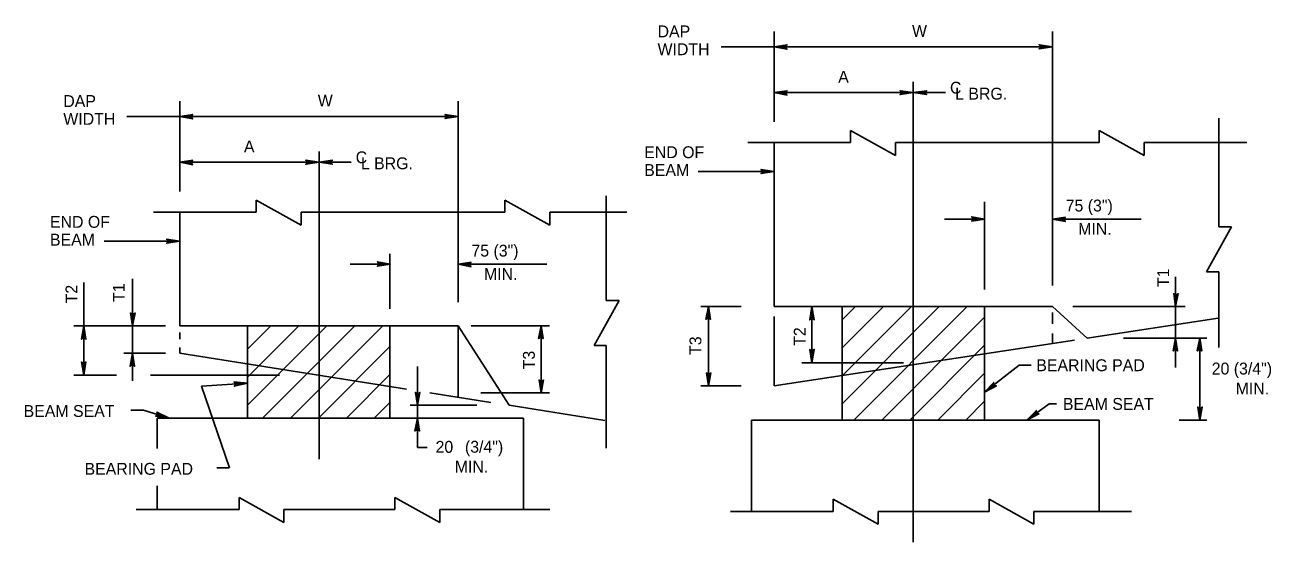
# Model space of a CAD drawing. Extents: x 637933 to 640019, y 298854 to 300042.
# Drawn here: x 639703.7 to 640018.8, y 299316.2 to 299446.8 of the extents above; entities that cross this region are included whole.
import ezdxf

# ---------------------------------------------------------------- set-up
doc = ezdxf.new("R2010")
doc.units = 0
doc.layers.add('1', color=7, linetype='Continuous')

msp = doc.modelspace()

# ---------------------------------------------------------------- linework, layer by layer
at = {"layer": '1'}
for p, q in [((639893.14, 299445.19), (639893.14, 299422.36)), ((639963.49, 299445.19), (639963.49, 299380.98)), ((639879.74, 299441.32), (639963.49, 299441.32)), ((639928.31, 299432.46), (639928.31, 299426.1)), ((639893.14, 299429.72), (639928.31, 299429.72)), ((639928.31, 299429.72), (639936.45, 299429.72)), ((639742.9, 299427.6), (639742.9, 299404.77)), ((639813.25, 299427.6), (639813.25, 299376.85)), ((639729.5, 299423.73), (639813.25, 299423.73)), ((639928.31, 299316.23), (639928.31, 299426.1)), ((640005.52, 299395.86), (640005.52, 299423.24)), ((639912.44, 299417.13), (639912.44, 299420.19)), ((639912.44, 299420.19), (639923.79, 299413.88)), ((639975.28, 299417.13), (639975.28, 299420.19)), ((639975.28, 299420.19), (639986.63, 299413.88)), ((639886.44, 299417.13), (639912.44, 299417.13)), ((639893.14, 299417.13), (639893.14, 299375.72)), ((639923.79, 299417.13), (639975.28, 299417.13)), ((639923.79, 299417.13), (639923.79, 299413.88)), ((639986.63, 299417.13), (639986.63, 299413.88)), ((639986.63, 299417.13), (640012.63, 299417.13)), ((639778.07, 299414.87), (639778.07, 299408.51)), ((639778.07, 299337.19), (639778.07, 299414.78)), ((639742.9, 299412.13), (639778.07, 299412.13)), ((639778.07, 299412.13), (639786.21, 299412.13)), ((639873.94, 299409.78), (639893.14, 299409.78)), ((639762.2, 299399.54), (639762.2, 299402.6)), ((639762.2, 299402.6), (639773.55, 299396.29)), ((639825.04, 299399.54), (639825.04, 299402.6)), ((639825.04, 299402.6), (639836.39, 299396.29)), ((639850.69, 299377.25), (639850.69, 299403.63)), ((639946.31, 299379.97), (639946.31, 299402.14)), ((639736.2, 299399.54), (639762.2, 299399.54)), ((639742.9, 299399.54), (639742.9, 299370.85)), ((639773.55, 299399.54), (639825.04, 299399.54)), ((639773.55, 299399.54), (639773.55, 299396.29)), ((639836.39, 299399.54), (639836.39, 299396.29)), ((639836.39, 299399.54), (639855.87, 299399.54)), ((639946.31, 299397.77), (639936.21, 299397.77)), ((639963.49, 299397.77), (639985.91, 299397.77)), ((640002.46, 299384.51), (640008.77, 299395.86)), ((640005.52, 299395.86), (640008.77, 299395.86)), ((639723.7, 299392.19), (639742.9, 299392.19)), ((639795.98, 299375.11), (639795.98, 299389.04)), ((639796.07, 299386.38), (639785.97, 299386.38)), ((639813.25, 299386.38), (639835.67, 299386.38)), ((639730.92, 299382.69), (639730.92, 299370.85)), ((639994.63, 299383.17), (639994.63, 299375.72)), ((640005.52, 299384.51), (640002.46, 299384.51)), ((640005.52, 299365.37), (640005.52, 299384.51)), ((639718.57, 299381.75), (639718.57, 299370.85)), ((639847.63, 299365.9), (639853.94, 299377.25)), ((639850.69, 299377.25), (639853.94, 299377.25)), ((639874.56, 299375.72), (639884.81, 299375.72)), ((639876.51, 299375.72), (639876.51, 299355.71)), ((639963.49, 299375.72), (639893.14, 299375.72)), ((639893.14, 299373.16), (639893.14, 299355.71)), ((639902.69, 299375.72), (639902.69, 299361.5)), ((639910.31, 299347.05), (639910.31, 299375.72)), ((639910.31, 299372.37), (639913.66, 299375.72)), ((639910.31, 299365.3), (639920.73, 299375.72)), ((639910.31, 299358.23), (639927.81, 299375.72)), ((639910.31, 299351.16), (639934.88, 299375.72)), ((639913.27, 299347.05), (639941.95, 299375.72)), ((639920.34, 299347.05), (639946.31, 299373.02)), ((639946.31, 299347.05), (639946.31, 299375.72)), ((639963.49, 299375.72), (639972.26, 299367.73)), ((639963.49, 299374.18), (639963.49, 299371.3)), ((639968.6, 299375.72), (639997.05, 299375.72)), ((639972.26, 299367.73), (640005.38, 299372.76)), ((639994.63, 299375.72), (639994.63, 299367.73)), ((639716.03, 299370.85), (639739.23, 299370.85)), ((639718.57, 299370.85), (639718.57, 299358.34)), ((639730.92, 299370.85), (639730.92, 299363.89)), ((639813.25, 299370.85), (639742.9, 299370.85)), ((639759.98, 299347.52), (639759.98, 299370.85)), ((639759.98, 299364.95), (639765.88, 299370.85)), ((639759.98, 299357.88), (639772.95, 299370.85)), ((639759.98, 299350.81), (639780.02, 299370.85)), ((639763.75, 299347.52), (639787.09, 299370.85)), ((639770.83, 299347.52), (639794.17, 299370.85)), ((639795.98, 299347.52), (639795.98, 299370.85)), ((639813.25, 299370.85), (639826.13, 299350.77)), ((639813.25, 299370.85), (639813.25, 299352.8)), ((639816.5, 299370.85), (639836.33, 299370.85)), ((639834.21, 299370.85), (639834.21, 299353.94)), ((639742.9, 299369.17), (639742.9, 299367.48)), ((639893.14, 299355.71), (639969.06, 299367.24)), ((639963.49, 299368.87), (639963.49, 299366.4)), ((639981.41, 299367.73), (640002.5, 299367.73)), ((639994.63, 299367.73), (639994.63, 299360.33)), ((640000.71, 299367.73), (640000.71, 299347.05)), ((639728.75, 299363.89), (639739.23, 299363.89)), ((639730.92, 299363.89), (639730.92, 299356.9)), ((639742.9, 299365.33), (639742.9, 299363.89)), ((639742.9, 299363.89), (639800.19, 299354.86)), ((639777.9, 299347.52), (639795.98, 299365.6)), ((639850.69, 299365.9), (639847.63, 299365.9)), ((639850.69, 299339.9), (639850.69, 299365.9)), ((639927.42, 299347.05), (639946.31, 299365.94)), ((639802.94, 299360.6), (639802.94, 299350.77)), ((639900.15, 299361.5), (639925.8, 299361.5)), ((639716.03, 299358.34), (639726.88, 299358.34)), ((639735.49, 299358.34), (639768.05, 299358.34)), ((639784.97, 299347.52), (639795.98, 299358.53)), ((639934.49, 299347.05), (639946.31, 299358.87)), ((639748.36, 299355.61), (639755.39, 299335)), ((639806.06, 299353.93), (639821.52, 299351.49)), ((639819, 299353.94), (639836.33, 299353.94)), ((639874.56, 299355.71), (639884.81, 299355.71)), ((639792.04, 299347.52), (639795.98, 299351.46)), ((639801.06, 299350.77), (639817.97, 299350.77)), ((639802.94, 299350.77), (639802.94, 299347.52)), ((639826.13, 299350.77), (639850.31, 299346.96)), ((639941.56, 299347.05), (639946.31, 299351.8)), ((639730.5, 299349.54), (639733.67, 299349.54)), ((639733.67, 299349.54), (639740.14, 299347.52)), ((639737.13, 299347.52), (639829.76, 299347.52)), ((639737.13, 299347.52), (639737.13, 299339.88)), ((639802.94, 299347.52), (639802.94, 299340.1)), ((639829.76, 299347.52), (639829.76, 299324.45)), ((639887.37, 299347.05), (639887.37, 299323.98)), ((639887.37, 299347.05), (639975.26, 299347.05)), ((639975.26, 299347.05), (639975.26, 299323.98)), ((640002.5, 299347.05), (639995.53, 299347.05)), ((639802.94, 299340.1), (639805.42, 299340.1)), ((639752.22, 299335), (639755.38, 299335)), ((639737.13, 299330.45), (639737.13, 299324.45)), ((639757.84, 299324.45), (639757.84, 299327.5)), ((639757.84, 299327.5), (639769.19, 299321.2)), ((639797.22, 299324.45), (639797.22, 299327.5)), ((639797.22, 299327.5), (639808.57, 299321.2)), ((639908.08, 299323.98), (639908.08, 299327.04)), ((639908.08, 299327.04), (639919.43, 299320.73)), ((639947.46, 299323.98), (639947.46, 299327.04)), ((639947.46, 299327.04), (639958.81, 299320.73)), ((639731.84, 299324.45), (639757.84, 299324.45)), ((639769.19, 299324.45), (639797.22, 299324.45)), ((639769.19, 299324.45), (639769.19, 299321.2)), ((639808.57, 299324.45), (639808.57, 299321.2)), ((639808.57, 299324.45), (639836.43, 299324.45)), ((639882.08, 299323.98), (639908.08, 299323.98)), ((639919.43, 299323.98), (639947.46, 299323.98)), ((639919.43, 299323.98), (639919.43, 299320.73)), ((639958.81, 299323.98), (639958.81, 299320.73)), ((639958.81, 299323.98), (639983.46, 299323.98))]:
    msp.add_line(p, q, dxfattribs=at)
for points in [[(639896.26, 299440.82), (639896.14, 299441.07), (639893.14, 299441.32), (639896.26, 299440.82), (639896.39, 299440.69), (639893.14, 299441.32), (639896.14, 299441.44), (639896.26, 299441.69), (639893.14, 299441.32), (639896.39, 299441.82), (639896.26, 299441.69)], [(639960.37, 299441.69), (639960.49, 299441.44), (639963.49, 299441.32), (639960.37, 299441.69), (639960.12, 299441.82), (639963.49, 299441.32), (639960.49, 299441.19), (639960.37, 299440.94), (639963.49, 299441.32), (639960.12, 299440.82), (639960.37, 299440.94)], [(639896.26, 299429.22), (639896.14, 299429.47), (639893.14, 299429.72), (639896.26, 299429.22), (639896.39, 299429.09), (639893.14, 299429.72), (639896.14, 299429.84), (639896.26, 299430.09), (639893.14, 299429.72), (639896.39, 299430.22), (639896.26, 299430.09)], [(639925.19, 299430.09), (639925.31, 299429.84), (639928.31, 299429.72), (639925.19, 299430.09), (639924.94, 299430.22), (639928.31, 299429.72), (639925.31, 299429.59), (639925.19, 299429.34), (639928.31, 299429.72), (639924.94, 299429.22), (639925.19, 299429.34)], [(639931.44, 299430.09), (639931.31, 299429.84), (639928.31, 299429.72), (639931.44, 299430.09), (639931.69, 299430.22), (639928.31, 299429.72), (639931.31, 299429.59), (639931.44, 299429.34), (639928.31, 299429.72), (639931.69, 299429.22), (639931.44, 299429.34)], [(639746.02, 299423.23), (639745.9, 299423.48), (639742.9, 299423.73), (639746.02, 299423.23), (639746.15, 299423.1), (639742.9, 299423.73), (639745.9, 299423.85), (639746.02, 299424.1), (639742.9, 299423.73), (639746.15, 299424.23), (639746.02, 299424.1)], [(639810.12, 299424.1), (639810.25, 299423.85), (639813.25, 299423.73), (639810.12, 299424.1), (639809.87, 299424.23), (639813.25, 299423.73), (639810.25, 299423.6), (639810.12, 299423.35), (639813.25, 299423.73), (639809.87, 299423.23), (639810.12, 299423.35)], [(639746.02, 299411.63), (639745.9, 299411.88), (639742.9, 299412.13), (639746.02, 299411.63), (639746.15, 299411.5), (639742.9, 299412.13), (639745.9, 299412.25), (639746.02, 299412.5), (639742.9, 299412.13), (639746.15, 299412.63), (639746.02, 299412.5)], [(639774.95, 299412.5), (639775.07, 299412.25), (639778.07, 299412.13), (639774.95, 299412.5), (639774.7, 299412.63), (639778.07, 299412.13), (639775.07, 299412), (639774.95, 299411.75), (639778.07, 299412.13), (639774.7, 299411.63), (639774.95, 299411.75)], [(639781.2, 299412.5), (639781.07, 299412.25), (639778.07, 299412.13), (639781.2, 299412.5), (639781.45, 299412.63), (639778.07, 299412.13), (639781.07, 299412), (639781.2, 299411.75), (639778.07, 299412.13), (639781.45, 299411.63), (639781.2, 299411.75)], [(639890.01, 299410.15), (639890.14, 299409.9), (639893.14, 299409.78), (639890.01, 299410.15), (639889.76, 299410.28), (639893.14, 299409.78), (639890.14, 299409.65), (639890.01, 299409.4), (639893.14, 299409.78), (639889.76, 299409.28), (639890.01, 299409.4)], [(639943.19, 299398.27), (639943.31, 299398.02), (639946.31, 299397.77), (639943.19, 299398.27), (639943.06, 299398.39), (639946.31, 299397.77), (639943.31, 299397.64), (639943.19, 299397.39), (639946.31, 299397.77), (639943.06, 299397.27), (639943.19, 299397.39)], [(639966.62, 299397.27), (639966.49, 299397.52), (639963.49, 299397.77), (639966.62, 299397.27), (639966.74, 299397.14), (639963.49, 299397.77), (639966.49, 299397.89), (639966.62, 299398.14), (639963.49, 299397.77), (639966.74, 299398.27), (639966.62, 299398.14)], [(639739.77, 299392.57), (639739.9, 299392.32), (639742.9, 299392.19), (639739.77, 299392.57), (639739.52, 299392.69), (639742.9, 299392.19), (639739.9, 299392.07), (639739.77, 299391.82), (639742.9, 299392.19), (639739.52, 299391.69), (639739.77, 299391.82)], [(639792.95, 299386.88), (639793.07, 299386.63), (639796.07, 299386.38), (639792.95, 299386.88), (639792.82, 299387), (639796.07, 299386.38), (639793.07, 299386.25), (639792.95, 299386), (639796.07, 299386.38), (639792.82, 299385.88), (639792.95, 299386)], [(639816.37, 299385.88), (639816.25, 299386.13), (639813.25, 299386.38), (639816.37, 299385.88), (639816.5, 299385.75), (639813.25, 299386.38), (639816.25, 299386.5), (639816.37, 299386.75), (639813.25, 299386.38), (639816.5, 299386.88), (639816.37, 299386.75)], [(639995.13, 299378.85), (639994.88, 299378.72), (639994.63, 299375.72), (639995.13, 299378.85), (639995.26, 299378.97), (639994.63, 299375.72), (639994.51, 299378.72), (639994.26, 299378.85), (639994.63, 299375.72), (639994.13, 299378.97), (639994.26, 299378.85)], [(639731.42, 299373.98), (639731.17, 299373.85), (639730.92, 299370.85), (639731.42, 299373.98), (639731.55, 299374.1), (639730.92, 299370.85), (639730.8, 299373.85), (639730.55, 299373.98), (639730.92, 299370.85), (639730.42, 299374.1), (639730.55, 299373.98)], [(639876.01, 299372.6), (639876.26, 299372.72), (639876.51, 299375.72), (639876.01, 299372.6), (639875.89, 299372.47), (639876.51, 299375.72), (639876.64, 299372.72), (639876.89, 299372.6), (639876.51, 299375.72), (639877.01, 299372.47), (639876.89, 299372.6)], [(639902.28, 299372.49), (639902.52, 299372.61), (639902.69, 299375.72), (639902.28, 299372.49), (639902.14, 299372.33), (639902.69, 299375.72), (639902.84, 299372.62), (639903.08, 299372.5), (639902.69, 299375.72), (639903.23, 299372.33), (639903.08, 299372.5)], [(639902.28, 299372.49), (639902.52, 299372.61), (639902.69, 299375.72), (639902.28, 299372.49), (639902.14, 299372.33), (639902.69, 299375.72), (639902.84, 299372.62), (639903.08, 299372.5), (639902.69, 299375.72), (639903.23, 299372.33), (639903.08, 299372.5)], [(639718.16, 299367.63), (639718.4, 299367.75), (639718.57, 299370.85), (639718.16, 299367.63), (639718.02, 299367.46), (639718.57, 299370.85), (639718.72, 299367.75), (639718.95, 299367.64), (639718.57, 299370.85), (639719.11, 299367.46), (639718.95, 299367.64)], [(639718.16, 299367.63), (639718.4, 299367.75), (639718.57, 299370.85), (639718.16, 299367.63), (639718.02, 299367.46), (639718.57, 299370.85), (639718.72, 299367.75), (639718.95, 299367.64), (639718.57, 299370.85), (639719.11, 299367.46), (639718.95, 299367.64)], [(639833.71, 299367.73), (639833.96, 299367.85), (639834.21, 299370.85), (639833.71, 299367.73), (639833.58, 299367.6), (639834.21, 299370.85), (639834.33, 299367.85), (639834.58, 299367.73), (639834.21, 299370.85), (639834.71, 299367.6), (639834.58, 299367.73)], [(639994.13, 299364.61), (639994.38, 299364.73), (639994.63, 299367.73), (639994.13, 299364.61), (639994.01, 299364.48), (639994.63, 299367.73), (639994.76, 299364.73), (639995.01, 299364.61), (639994.63, 299367.73), (639995.13, 299364.48), (639995.01, 299364.61)], [(640000.21, 299364.6), (640000.46, 299364.73), (640000.71, 299367.73), (640000.21, 299364.6), (640000.09, 299364.48), (640000.71, 299367.73), (640000.84, 299364.73), (640001.09, 299364.6), (640000.71, 299367.73), (640001.21, 299364.48), (640001.09, 299364.6)], [(639730.42, 299360.76), (639730.67, 299360.89), (639730.92, 299363.89), (639730.42, 299360.76), (639730.3, 299360.64), (639730.92, 299363.89), (639731.05, 299360.89), (639731.3, 299360.76), (639730.92, 299363.89), (639731.42, 299360.64), (639731.3, 299360.76)], [(639903.09, 299364.73), (639902.86, 299364.61), (639902.69, 299361.5), (639903.09, 299364.73), (639903.24, 299364.89), (639902.69, 299361.5), (639902.54, 299364.6), (639902.31, 299364.72), (639902.69, 299361.5), (639902.15, 299364.89), (639902.31, 299364.72)], [(639903.09, 299364.73), (639902.86, 299364.61), (639902.69, 299361.5), (639903.09, 299364.73), (639903.24, 299364.89), (639902.69, 299361.5), (639902.54, 299364.6), (639902.31, 299364.72), (639902.69, 299361.5), (639902.15, 299364.89), (639902.31, 299364.72)], [(639718.97, 299361.57), (639718.74, 299361.45), (639718.57, 299358.34), (639718.97, 299361.57), (639719.12, 299361.74), (639718.57, 299358.34), (639718.42, 299361.45), (639718.18, 299361.56), (639718.57, 299358.34), (639718.03, 299361.74), (639718.18, 299361.56)], [(639958.11, 299360.88), (639955.03, 299360.88), (639946.31, 299354.04)], [(639834.71, 299357.06), (639834.46, 299356.94), (639834.21, 299353.94), (639834.71, 299357.06), (639834.83, 299357.19), (639834.21, 299353.94), (639834.08, 299356.94), (639833.83, 299357.06), (639834.21, 299353.94), (639833.71, 299357.19), (639833.83, 299357.06)], [(639877.01, 299358.84), (639876.76, 299358.71), (639876.51, 299355.71), (639877.01, 299358.84), (639877.14, 299358.96), (639876.51, 299355.71), (639876.39, 299358.71), (639876.14, 299358.84), (639876.51, 299355.71), (639876.01, 299358.96), (639876.14, 299358.84)], [(639748.36, 299355.61), (639759.98, 299356.33)], [(639756.73, 299356.52), (639756.87, 299356.3), (639759.98, 299356.33), (639756.73, 299356.52), (639756.56, 299356.65), (639759.98, 299356.33), (639756.89, 299355.97), (639756.79, 299355.74), (639759.98, 299356.33), (639756.63, 299355.57), (639756.79, 299355.74)], [(639803.44, 299353.89), (639803.19, 299353.77), (639802.94, 299350.77), (639803.44, 299353.89), (639803.57, 299354.02), (639802.94, 299350.77), (639802.82, 299353.77), (639802.57, 299353.89), (639802.94, 299350.77), (639802.44, 299354.02), (639802.57, 299353.89)], [(639949.11, 299355.72), (639948.87, 299355.83), (639946.31, 299354.04), (639949.11, 299355.72), (639949.32, 299355.71), (639946.31, 299354.04), (639948.66, 299356.08), (639948.61, 299356.33), (639946.31, 299354.04), (639948.65, 299356.56), (639948.61, 299356.33)], [(639949.11, 299355.72), (639948.87, 299355.83), (639946.31, 299354.04), (639949.11, 299355.72), (639949.32, 299355.71), (639946.31, 299354.04), (639948.66, 299356.08), (639948.61, 299356.33), (639946.31, 299354.04), (639948.65, 299356.56), (639948.61, 299356.33)], [(639964.52, 299351.15), (639962.63, 299351.15), (639956.99, 299347.05)], [(639737.18, 299348.88), (639737.22, 299348.62), (639740.14, 299347.52), (639737.18, 299348.88), (639737.07, 299349.07), (639740.14, 299347.52), (639737.13, 299348.31), (639736.95, 299348.12), (639740.14, 299347.52), (639736.74, 299348.03), (639736.95, 299348.12)], [(639802.44, 299344.39), (639802.69, 299344.52), (639802.94, 299347.52), (639802.44, 299344.39), (639802.32, 299344.27), (639802.94, 299347.52), (639803.07, 299344.52), (639803.32, 299344.39), (639802.94, 299347.52), (639803.44, 299344.27), (639803.32, 299344.39)], [(639959.84, 299348.62), (639959.61, 299348.74), (639956.99, 299347.05), (639959.84, 299348.62), (639960.06, 299348.6), (639956.99, 299347.05), (639959.42, 299349), (639959.37, 299349.25), (639956.99, 299347.05), (639959.42, 299349.48), (639959.37, 299349.25)], [(640001.21, 299350.17), (640000.96, 299350.05), (640000.71, 299347.05), (640001.21, 299350.17), (640001.34, 299350.3), (640000.71, 299347.05), (640000.59, 299350.05), (640000.34, 299350.17), (640000.71, 299347.05), (640000.21, 299350.3), (640000.34, 299350.17)]]:
    msp.add_lwpolyline(points, dxfattribs=at)

# ---------------------------------------------------------------- texts
for s, p in [('DAP', (639863.65, 299443.69)), ('W', (639927.98, 299443.82)), ('WIDTH', (639863.65, 299439.19)), ('A', (639909.32, 299432.22)), ('C', (639937.57, 299429.47)), ('L BRG.', (639938.88, 299427.97)), ('DAP', (639713.41, 299426.1)), ('W', (639777.74, 299426.23)), ('WIDTH', (639713.41, 299421.6)), ('A', (639759.08, 299414.63)), ('C', (639787.33, 299411.88)), ('END OF', (639860.28, 299413.18)), ('L BRG.', (639788.64, 299410.38)), ('BEAM', (639860.28, 299408.68)), ('75 (3")', (639966.83, 299399.71)), ('END OF', (639710.04, 299395.59)), ('MIN.', (639970, 299393.82)), ('BEAM', (639710.04, 299391.09)), ('75 (3")', (639816.59, 299388.32)), ('MIN.', (639819.76, 299382.43)), ('BEARING PAD', (639959.4, 299359.38)), ('20 (3/4")', (640003.75, 299358.54)), ('MIN.', (640009.8, 299353.52)), ('BEAM SEAT', (639703.38, 299347.82)), ('BEAM SEAT', (639966.13, 299349.61)), ('20', (639807.52, 299338.77)), ('(3/4")', (639814.95, 299338.79)), ('BEARING PAD', (639718.78, 299333.22)), ('MIN.', (639812.38, 299333.77))]:
    msp.add_text(s, height=3, dxfattribs=at).set_placement(p)
for s, p in [('T1', (639992.98, 299380.63)), ('T2', (639716.97, 299376.51)), ('T1', (639728.94, 299376.88)), ('T2', (639901.09, 299365.78)), ('T3', (639874.72, 299363.49)), ('T3', (639832.62, 299359.85))]:
    msp.add_text(s, height=3, rotation=90, dxfattribs=at).set_placement(p)

doc.saveas('drawing.dxf')
